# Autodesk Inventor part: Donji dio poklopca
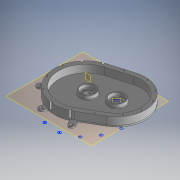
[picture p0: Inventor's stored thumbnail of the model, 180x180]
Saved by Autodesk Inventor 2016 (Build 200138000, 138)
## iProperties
Created: 2015-08
Part Number: Donji dio poklopca
Material: Generic
Document SubType Name: Modeling
Designer: stank
Density: 1 g/cm^3
Appearance: Default
Mass: 562.42 g
Surface Area: 1698.3 cm^2
Volume: 562.42 cm^3
Author: stank
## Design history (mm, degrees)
workplane "Work Plane1"
sketch "Sketch1" dims "d90" = 110
  geometry: L1 (-52.064, 118.882)-(-46.649, 108.689); L2 (-69.726, 109.498)-(-64.594, 99.838); L3 (-126.994, 39.663)-(-113.16, 35.428); L4 (-121.14, 58.787)-(-106.065, 54.173); L5 (-55.023, -107.864)-(-51.039, -94.851); L6 (-35.899, -113.718)-(-32.045, -101.129); L7 (48.505, -113.045)-(38.432, -94.085); L8 (66.167, -103.661)-(55.968, -84.464); L9 (-122.49, -36.299)-(-111.027, -30.209); L10 (-113.107, -53.961)-(-102.732, -48.449); L11 (-28.293, 54.626)-(47.33, 87.499) reference; L12 (89.587, -9.714)-(13.964, -42.586) reference; L13 (48.598, -88.799)-(119.152, -47.306); L14 (-38.458, 111.475)-(40.01, 134.76); L15 (-34.191, 97.094)-(44.277, 120.38); L16 (111.548, -34.377)-(40.994, -75.869); C1 r 4.5 at (-60.895, 114.19) reference; C2 r 4.5 at (-124.067, 49.225) reference; C3 r 4.5 at (-117.798, -45.13) reference; C4 r 4.5 at (-45.461, -110.791) reference; C5 r 4.5 at (57.336, -108.353) reference; A1 r 10 centre (-60.895, 114.19) between (-52.064, 118.882) and (-69.726, 109.498) reference; A2 r 10 centre (-124.067, 49.225) between (-121.14, 58.787) and (-126.994, 39.663) reference; A3 r 10 centre (-117.798, -45.13) between (-122.49, -36.299) and (-113.107, -53.961) reference; A4 r 10 centre (-45.461, -110.791) between (-55.023, -107.864) and (-35.899, -113.718) reference; A5 r 10 centre (57.336, -108.353) between (48.505, -113.045) and (66.167, -103.661) reference; A6 r 53 centre (-7.164, 6.02) between (-28.293, 54.626) and (13.964, -42.586) reference; A7 r 53 centre (68.459, 38.892) between (89.587, -9.714) and (47.33, 87.499) reference; A8 r 100 centre (68.459, 38.892) between (119.152, -47.306) and (40.01, 134.76); A9 r 95 centre (-7.164, 6.02) between (-34.191, 97.094) and (40.994, -75.869); A10 r 85 centre (68.459, 38.892) between (111.548, -34.377) and (44.277, 120.38)
  constraints: 28 end point, 10 tangent, 6 point on circle, 3 centre point, 2 coincident, 2 parallel, 1 point on line, 18 other
  dimensions: "d91" = 100 radius of A8; "d92" = 15 dimension on A9
extrude "Extrusion1" new body sketch "Sketch1" distance "d0" = 5; taper "d1" = 0 deg
sketch "Sketch2"
  geometry: L1 (-34.191, 97.094)-(44.277, 120.38) reference; L2 (111.548, -34.377)-(40.994, -75.869) reference; L3 (-38.458, 111.475)-(40.01, 134.76); L4 (119.152, -47.306)-(48.598, -88.799); A1 r 95 centre (-7.164, 6.02) between (-34.191, 97.094) and (40.994, -75.869) reference; A2 r 85 centre (68.459, 38.892) between (111.548, -34.377) and (44.277, 120.38) reference; A3 r 110 centre (-7.164, 6.02) between (-38.458, 111.475) and (48.598, -88.799); A4 r 100 centre (68.459, 38.892) between (119.152, -47.306) and (40.01, 134.76)
  constraints: 8 end point, 8 point on circle, 4 centre point, 13 other
  dimensions: "d93" = 15 radial gap between concentric circles of A1 A3
workplane "Work Plane2"
sketch "Sketch3"
  geometry: L1 (-48.598, -88.799)-(-119.152, -47.306); L2 (-40.01, 134.76)-(38.458, 111.475); L3 (38.458, 111.475)-(-40.01, 134.76) reference; L4 (-119.152, -47.306)-(-48.598, -88.799) reference; C1 r 7.5 at (7.41, 13.516) reference; A1 r 110 centre (7.164, 6.02) between (-48.598, -88.799) and (38.458, 111.475); A2 r 100 centre (-68.459, 38.892) between (-40.01, 134.76) and (-119.152, -47.306); A3 r 100 centre (-68.459, 38.892) between (-40.01, 134.76) and (-119.152, -47.306) reference; A4 r 110 centre (7.164, 6.02) between (89.616, 78.833) and (51.64, 106.628) reference; 1 further point
  constraints: 4 end point, 4 point on circle, 4 tangent, 2 centre point, 2 collinear, 2 concentric
extrude "Extrusion3" join sketch "Sketch3" distance "d4" = 5; taper "d5" = 0 deg
workplane "Work Plane4"
sketch "Sketch5"
  geometry: L1 (50, -31.888)-(50, 44.669); L2 (50, -15)-(49, -15); L3 (49, -15)-(49, -16); L4 (49, -16)-(50, -16); L5 (50, -23.5)-(37, -23.5); L6 (37, -23.5)-(37, -26.5); L7 (37, -26.5)-(50, -26.5); L8 (50, -7.5)-(50, 7.5) reference; L9 (50, 0)-(42.201, 0); L10 (50, -15)-(50, -16); L11 (50, -23.5)-(50, -26.5); 1 further point
  constraints: 20 end point, 4 perpendicular, 2 horizontal, 1 midpoint, 1 point on line
  dimensions: "d7" = 15 distance from line of L9.start L2; "d8" = 1 distance of L2.end L3.end; "d9" = 23.5 distance from line of L9.start L5; "d10" = 3 distance between parallel lines of L5 L7; "d12" = 1 distance from line of L2.start L3
workplane "Work Plane5"
sketch "Sketch6" dims "d7" = 15, "d8" = 1, "d9" = 23.5, "d10" = 3, "d12" = 1
  geometry: L1 (1, 13)-(0, 13); L2 (0, 13)-(0, 14); L3 (0, 14)-(1, 14); L4 (1, 23.5)-(-12, 23.5); L5 (-12, 23.5)-(-12, 27.5); L6 (-12, 27.5)-(1, 27.5); L7 (1, 27.5)-(1, 13); L8 (1, 42.026)-(1, -32.784); L9 (0, 0)-(-15.466, 0) reference; 1 further point
  constraints: 18 end point, 4 horizontal, 4 perpendicular, 2 point on line, 1 collinear
  dimensions: "d15" = 13 distance between parallel lines of L9 L1; "d16" = 1 distance of L1.end L2.end; "d17" = 1 distance of L2.end L3.end; "d18" = 13 distance of L4.start L4.end; "d19" = 4 distance of L4.end L5.end; "d20" = 23.5 distance from line of L9.end L4
revolve "Revolution2" stored, may be unused: angle "d14" = 90 deg
revolve "Revolution3" stored, may be unused: angle "d21" = 90 deg
fillet "Fillet1" dims "d22" = 2
fillet "Fillet4" dims "d44" = 2
extrude "Extrusion4" join sketch "Sketch2" distance "d78" = 26; taper "d79" = 0 deg
sketch "Sketch8"
  geometry: L1 (81.85, 31)-(0, 31) reference; L2 (81.85, 31)-(81.85, 0) reference; 1 further point
  dimensions: "d117" = 15 distance from line of L1 point (66.85, 16); "d118" = 15 distance from line of L2 point (66.85, 16)
chamfer "Chamfer3" distance "d87" = 2; stored, may be unused: second distance "d88" = 2, angle "d89" = 45 deg
sketch "Sketch10"
  geometry: L1 (-34.191, 97.094)-(44.277, 120.38) reference; L2 (111.548, -34.377)-(40.994, -75.869) reference; L3 (-36.325, 104.285)-(42.143, 127.57); L4 (115.35, -40.842)-(44.796, -82.334); L5 (-101.167, -34.842)-(-7.164, 6.02); L6 (-7.164, 6.02)-(-68.142, -76.369); L7 (-7.164, 6.02)-(-18.778, -95.82); L8 (-7.164, 6.02)-(33.698, -87.983); L9 (-7.164, 6.02)-(-109.004, 17.634); L10 (-7.164, 6.02)-(-89.553, 66.998); L11 (-7.164, 6.02)-(-48.026, 100.023); L12 (68.459, 38.892)-(78.94, 130.797); L13 (68.459, 38.892)-(123.488, 113.243); L14 (68.459, 38.892)-(153.291, 75.768); L15 (68.459, 38.892)-(160.363, 28.411); L16 (68.459, 38.892)-(142.81, -16.137); L17 (68.459, 38.892)-(-7.164, 6.02); C1 r 13 at (68.459, 38.892) reference; A1 r 95 centre (-7.164, 6.02) between (-34.191, 97.094) and (40.994, -75.869) reference; A2 r 85 centre (68.459, 38.892) between (111.548, -34.377) and (44.277, 120.38) reference; A3 r 92.5 centre (68.459, 38.892) between (115.35, -40.842) and (42.143, 127.57); 3 further points
  constraints: 30 end point, 7 point on circle, 2 midpoint, 1 centre point, 1 collinear, 1 perpendicular, 14 other
  dimensions: "d94" = 7.5 dimension on A1; "d95" = 30 deg angle of L11 L10; "d97" = 30 deg angle of L10 L9; "d102" = 30 deg angle of L7 L8; "d104" = 30 deg angle of L6 L7; "d105" = 30 deg angle of L5 L6; "d106" = 30 deg angle of L13 L14; "d107" = 30 deg angle of L12 L13; "d108" = 30 deg angle of L14 L15; "d109" = 30 deg angle of L15 L16
hole "Hole4" sketch "Sketch10" at (-101.167, -34.842), (-109.004, 17.634), (-89.553, 66.998), (-48.026, 100.023), (78.94, 130.797), (123.488, 113.243), (153.291, 75.768), (160.363, 28.411), (142.81, -16.137), (33.698, -87.983), (-18.778, -95.82), (-68.142, -76.369)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 diameter "d110" = 8; stored, may be unused: countersink angle "d114" = 90 deg, drill point angle "d116" = 118 deg; dims "d111" = 6, "d112" = 4, "d113" = 2, "d115" = 25
hole "Hole5" sketch "Sketch8" diameter "d119" = 20; stored, may be unused: countersink angle "d123" = 90 deg, drill point angle "d125" = 118 deg; dims "d120" = 6, "d121" = 4, "d122" = 2, "d124" = 25
body "Solid1"
node "Reference12"
node "Reference23"
node "Reference24"
node "Reference25"
node "Reference26"
node "Reference27"
node "Reference28"
node "Reference29"
node "Reference30"
node "Reference31"
node "Reference32"
node "Reference66"
node "Reference69"
node "Reference70"
node "Reference71"
node "Reference72"
node "Reference73"
node "Reference74"
node "Reference75"
node "Reference76"
node "Reference77"
node "Reference78"
node "Reference79"
